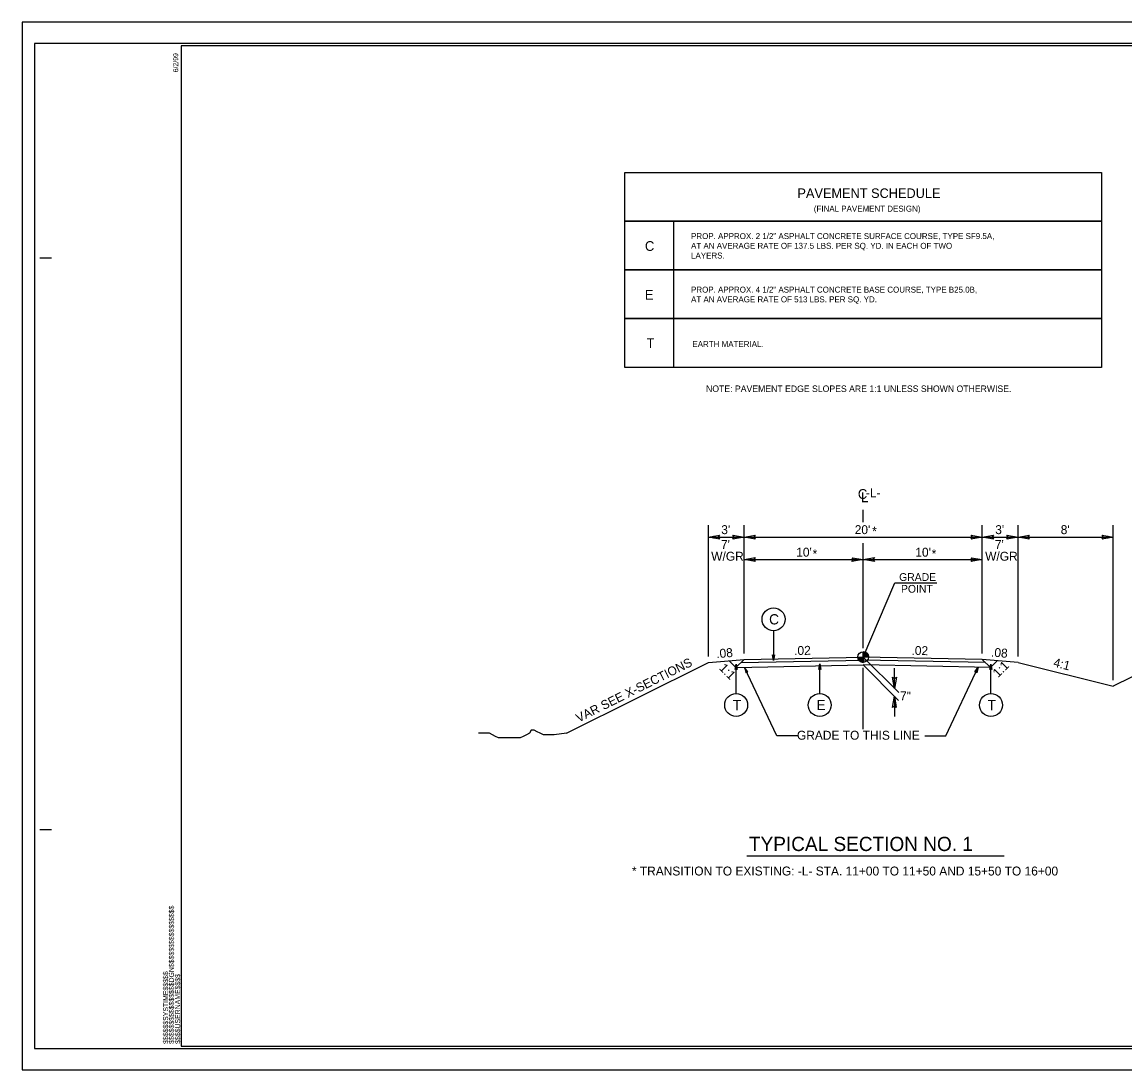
# Model space of a CAD drawing. Extents: x 573793 to 573946, y -53322 to -53234.
# Drawn here: x 573793.4 to 573886, y -53321.6 to -53233.6 of the extents above; entities that cross this region are included whole.
import ezdxf

# ---------------------------------------------------------------- set-up
doc = ezdxf.new("R2010")
doc.units = 0
for name, color, linetype in [('Prop Pavement Schedule Description CELL', 7, 'Continuous'), ('Sheet Cutting Line CELL', 7, 'Continuous'), ('Sheet Plot Border Inside CELL', 7, 'Continuous'), ('Sheet Plot Border Outside CELL', 7, 'Continuous'), ('Sheet Typical CELL', 7, 'Continuous'), ('Typical Grade Point Symbol CELL', 7, 'Continuous'), ('Typical ID Circle CELL', 7, 'Continuous'), ('Typical Pavement Slope CELL', 7, 'Continuous'), ('Typical Pavement Slope Information CELL', 7, 'Continuous'), ('Typical Shoulder Slope CELL', 7, 'Continuous'), ('Typical Slope Point Local CELL', 7, 'Continuous'), ('Typical Terminator CELL', 7, 'Continuous'), ('Typical Text Centerline CELL', 7, 'Continuous'), ('Typical Text General CELL', 7, 'Continuous'), ('Typical Text Grade Point CELL', 7, 'Continuous'), ('Typical Text ID Circle CELL', 7, 'Continuous'), ('Typical Text Label CELL', 7, 'Continuous')]:
    doc.layers.add(name, color=color, linetype=linetype)

msp = doc.modelspace()

# ---------------------------------------------------------------- linework, layer by layer
at = {"layer": 'Prop Pavement Schedule Description CELL'}
msp.add_line((573848.075, -53262.553), (573848.075, -53262.553), dxfattribs=at)
msp.add_lwpolyline([(573843.984, -53246.188), (573883.985, -53246.188), (573883.985, -53250.279), (573843.984, -53250.279)], close=True, dxfattribs=at)
for points in [[(573848.075, -53254.371), (573843.984, -53254.371), (573843.984, -53250.279), (573883.984, -53250.279), (573883.984, -53254.371), (573848.075, -53254.371), (573848.075, -53250.279)], [(573848.075, -53258.462), (573843.984, -53258.462), (573843.984, -53254.371), (573883.984, -53254.371), (573883.984, -53258.462), (573848.075, -53258.462), (573848.075, -53254.371)], [(573848.075, -53262.553), (573843.984, -53262.553), (573843.984, -53258.462), (573883.984, -53258.462), (573883.984, -53262.553), (573848.075, -53262.553), (573848.075, -53258.462)]]:
    msp.add_lwpolyline(points, dxfattribs=at)
at = {"layer": 'Sheet Cutting Line CELL'}
for p, q in [((573928.086, -53233.554), (573793.366, -53233.554)), ((573793.366, -53233.554), (573793.366, -53321.554)), ((573793.366, -53321.554), (573928.086, -53321.554))]:
    msp.add_line(p, q, dxfattribs=at)
at = {"layer": 'Sheet Plot Border Inside CELL'}
msp.add_lwpolyline([(573927.726, -53235.35), (573794.406, -53235.35), (573794.406, -53319.758), (573927.726, -53319.758)], close=True, dxfattribs=at)
at = {"layer": 'Sheet Plot Border Outside CELL'}
msp.add_lwpolyline([(573928.086, -53233.554), (573793.366, -53233.554), (573793.366, -53321.554), (573928.086, -53321.554)], close=True, dxfattribs=at)
at = {"layer": 'Sheet Typical CELL'}
for p, q in [((573794.846, -53253.354), (573795.846, -53253.354)), ((573794.846, -53301.354), (573795.846, -53301.354)), ((573806.726, -53319.554), (573806.726, -53319.554)), ((573806.726, -53319.554), (573806.726, -53319.554)), ((573806.726, -53319.554), (573806.726, -53319.554)), ((573806.726, -53319.554), (573806.726, -53319.554)), ((573806.726, -53319.554), (573806.726, -53319.554)), ((573806.726, -53319.554), (573806.726, -53319.554))]:
    msp.add_line(p, q, dxfattribs=at)
msp.add_lwpolyline([(573926.726, -53235.554), (573806.726, -53235.554), (573806.726, -53319.554), (573926.726, -53319.554)], close=True, dxfattribs=at)
msp.add_lwpolyline([(573809.726, -53319.554), (573809.726, -53319.554)], dxfattribs=at)
at = {"layer": 'Typical Grade Point Symbol CELL'}
for p, q in [((573863.537, -53286.879), (573863.984, -53286.879)), ((573863.983, -53287.326), (573863.984, -53286.879)), ((573863.984, -53286.879), (573863.983, -53287.326)), ((573863.984, -53286.879), (573863.984, -53286.431)), ((573864.432, -53286.879), (573863.984, -53286.879))]:
    msp.add_line(p, q, dxfattribs=at)
for points in [[(573863.539, -53286.879), (573863.539, -53286.928)], [(573863.548, -53286.879), (573863.548, -53286.98)], [(573863.557, -53286.879), (573863.557, -53287.012)], [(573863.566, -53286.879), (573863.566, -53287.039)], [(573863.575, -53286.879), (573863.575, -53287.06)], [(573863.584, -53286.879), (573863.584, -53287.079)], [(573863.593, -53286.879), (573863.593, -53287.096)], [(573863.602, -53286.879), (573863.602, -53287.112)], [(573863.611, -53286.879), (573863.611, -53287.126)], [(573863.619, -53286.879), (573863.619, -53287.138)], [(573863.628, -53286.879), (573863.628, -53287.15)], [(573863.637, -53286.879), (573863.637, -53287.161)], [(573863.646, -53286.879), (573863.646, -53287.172)], [(573863.655, -53286.879), (573863.655, -53287.182)], [(573863.664, -53286.879), (573863.664, -53287.192)], [(573863.673, -53286.879), (573863.673, -53287.201)], [(573863.682, -53286.879), (573863.682, -53287.209)], [(573863.691, -53286.879), (573863.691, -53287.217)], [(573863.7, -53286.879), (573863.7, -53287.225)], [(573863.709, -53286.879), (573863.709, -53287.232)], [(573863.718, -53286.879), (573863.718, -53287.239)], [(573863.727, -53286.879), (573863.727, -53287.245)], [(573863.736, -53286.879), (573863.736, -53287.251)], [(573863.745, -53286.879), (573863.745, -53287.257)], [(573863.754, -53286.879), (573863.754, -53287.263)], [(573863.763, -53286.879), (573863.763, -53287.268)], [(573863.772, -53286.879), (573863.772, -53287.273)], [(573863.781, -53286.879), (573863.781, -53287.278)], [(573863.79, -53286.879), (573863.79, -53287.282)], [(573863.798, -53286.879), (573863.798, -53287.286)], [(573863.807, -53286.879), (573863.807, -53287.29)], [(573863.816, -53286.879), (573863.816, -53287.294)], [(573863.825, -53286.879), (573863.825, -53287.298)], [(573863.834, -53286.879), (573863.834, -53287.301)], [(573863.843, -53286.879), (573863.843, -53287.304)], [(573863.852, -53286.879), (573863.852, -53287.307)], [(573863.861, -53286.879), (573863.861, -53287.309)], [(573863.87, -53286.879), (573863.87, -53287.312)], [(573863.879, -53286.879), (573863.879, -53287.314)], [(573863.888, -53286.879), (573863.888, -53287.316)], [(573863.897, -53286.879), (573863.897, -53287.318)], [(573863.906, -53286.879), (573863.906, -53287.319)], [(573863.915, -53286.879), (573863.915, -53287.32)], [(573863.924, -53286.879), (573863.924, -53287.322)], [(573863.933, -53286.879), (573863.933, -53287.323)], [(573863.942, -53286.879), (573863.942, -53287.324)], [(573863.951, -53286.879), (573863.951, -53287.325)], [(573863.96, -53286.879), (573863.96, -53287.325)], [(573863.969, -53286.879), (573863.969, -53287.326)], [(573863.978, -53286.879), (573863.978, -53287.326), (573863.978, -53287.326)], [(573863.988, -53286.431), (573863.988, -53286.431), (573863.988, -53286.879)], [(573863.997, -53286.431), (573863.997, -53286.879)], [(573864.006, -53286.432), (573864.006, -53286.879)], [(573864.015, -53286.432), (573864.015, -53286.879)], [(573864.024, -53286.433), (573864.024, -53286.879)], [(573864.033, -53286.434), (573864.033, -53286.879)], [(573864.042, -53286.435), (573864.042, -53286.879)], [(573864.051, -53286.436), (573864.051, -53286.879)], [(573864.06, -53286.437), (573864.06, -53286.879)], [(573864.069, -53286.439), (573864.069, -53286.879)], [(573864.078, -53286.441), (573864.078, -53286.879)], [(573864.087, -53286.443), (573864.087, -53286.879)], [(573864.096, -53286.445), (573864.096, -53286.879)], [(573864.105, -53286.448), (573864.105, -53286.879)], [(573864.114, -53286.45), (573864.114, -53286.879)], [(573864.123, -53286.453), (573864.123, -53286.879)], [(573864.132, -53286.456), (573864.132, -53286.879)], [(573864.141, -53286.459), (573864.141, -53286.879)], [(573864.15, -53286.463), (573864.15, -53286.879)], [(573864.159, -53286.467), (573864.159, -53286.879)], [(573864.167, -53286.471), (573864.167, -53286.879)], [(573864.176, -53286.475), (573864.176, -53286.879)], [(573864.185, -53286.479), (573864.185, -53286.879)], [(573864.194, -53286.484), (573864.194, -53286.879)], [(573864.203, -53286.489), (573864.203, -53286.879)], [(573864.212, -53286.494), (573864.212, -53286.879)], [(573864.221, -53286.499), (573864.221, -53286.879)], [(573864.23, -53286.505), (573864.23, -53286.879)], [(573864.239, -53286.511), (573864.239, -53286.879)], [(573864.248, -53286.518), (573864.248, -53286.879)], [(573864.257, -53286.524), (573864.257, -53286.879)], [(573864.266, -53286.531), (573864.266, -53286.879)], [(573864.275, -53286.539), (573864.275, -53286.879)], [(573864.284, -53286.547), (573864.284, -53286.879)], [(573864.293, -53286.555), (573864.293, -53286.879)], [(573864.302, -53286.564), (573864.302, -53286.879)], [(573864.311, -53286.573), (573864.311, -53286.879)], [(573864.32, -53286.582), (573864.32, -53286.879)], [(573864.329, -53286.593), (573864.329, -53286.879)], [(573864.338, -53286.604), (573864.338, -53286.879)], [(573864.347, -53286.616), (573864.347, -53286.879)], [(573864.355, -53286.629), (573864.355, -53286.879)], [(573864.364, -53286.643), (573864.364, -53286.879)], [(573864.373, -53286.658), (573864.373, -53286.879)], [(573864.382, -53286.674), (573864.382, -53286.879)], [(573864.391, -53286.693), (573864.391, -53286.879)], [(573864.4, -53286.714), (573864.4, -53286.879)], [(573864.409, -53286.739), (573864.409, -53286.879)], [(573864.418, -53286.769), (573864.418, -53286.879)], [(573864.427, -53286.815), (573864.427, -53286.879)]]:
    msp.add_lwpolyline(points, dxfattribs=at)
msp.add_circle((573863.984, -53286.879), 0.448, dxfattribs=at)
for start, end in [(179.99048, 269.99048), (359.99048, 89.99048)]:
    msp.add_arc((573863.984, -53286.879), 0.448, start, end, dxfattribs=at)
at = {"layer": 'Typical ID Circle CELL'}
for p, q in [((573856.458, -53284.671), (573856.458, -53287.156)), ((573853.318, -53289.948), (573853.318, -53287.463)), ((573860.337, -53289.947), (573860.337, -53287.461)), ((573874.709, -53289.948), (573874.709, -53287.463))]:
    msp.add_line(p, q, dxfattribs=at)
for centre in [(573856.458, -53283.709), (573853.318, -53290.91), (573860.337, -53290.908), (573874.709, -53290.91)]:
    msp.add_circle(centre, 0.962, dxfattribs=at)
at = {"layer": 'Typical Pavement Slope CELL'}
for p, q in [((573853.984, -53287.079), (573863.984, -53286.879)), ((573873.984, -53287.079), (573863.984, -53286.879)), ((573852.728, -53287.184), (573853.304, -53287.759)), ((573853.984, -53287.079), (573853.304, -53287.759)), ((573853.304, -53287.759), (573863.998, -53287.545)), ((573853.728, -53287.335), (573863.989, -53287.13)), ((573874.665, -53287.759), (573863.971, -53287.545)), ((573874.241, -53287.335), (573863.989, -53287.13)), ((573873.984, -53287.079), (573874.665, -53287.759)), ((573875.241, -53287.184), (573874.665, -53287.759))]:
    msp.add_line(p, q, dxfattribs=at)
at = {"layer": 'Typical Pavement Slope Information CELL'}
for p, q in [((573863.984, -53275.55), (573863.984, -53274.508)), ((573850.984, -53286.829), (573850.984, -53275.791)), ((573853.984, -53286.579), (573853.984, -53275.791)), ((573873.984, -53286.579), (573873.984, -53275.791)), ((573876.984, -53286.829), (573876.984, -53275.791)), ((573884.984, -53288.828), (573884.984, -53275.791)), ((573850.984, -53276.807), (573853.984, -53276.807)), ((573853.984, -53276.807), (573873.984, -53276.807)), ((573863.984, -53286.129), (573863.984, -53277.302)), ((573873.984, -53276.807), (573876.984, -53276.807)), ((573876.984, -53276.807), (573884.984, -53276.807)), ((573853.984, -53278.699), (573863.984, -53278.699)), ((573863.984, -53278.699), (573873.984, -53278.699)), ((573863.984, -53286.879), (573866.638, -53280.643)), ((573863.984, -53286.879), (573866.966, -53289.861)), ((573856.744, -53293.486), (573854.02, -53287.745)), ((573863.971, -53287.545), (573866.953, -53290.527)), ((573863.984, -53292.931), (573863.984, -53287.795)), ((573866.613, -53289.507), (573866.613, -53287.813)), ((573870.913, -53293.486), (573873.64, -53287.739)), ((573866.599, -53290.174), (573866.599, -53291.867)), ((573858.496, -53293.486), (573856.744, -53293.486)), ((573869.161, -53293.486), (573870.913, -53293.486))]:
    msp.add_line(p, q, dxfattribs=at)
at = {"layer": 'Typical Shoulder Slope CELL'}
for p, q in [((573850.984, -53287.329), (573853.984, -53287.079)), ((573876.984, -53287.329), (573873.984, -53287.079))]:
    msp.add_line(p, q, dxfattribs=at)
at = {"layer": 'Typical Slope Point Local CELL'}
for p, q in [((573898.6, -53282.52), (573884.983, -53289.328)), ((573839.081, -53293.281), (573850.984, -53287.329)), ((573876.984, -53287.329), (573884.983, -53289.328))]:
    msp.add_line(p, q, dxfattribs=at)
msp.add_lwpolyline([(573839.081, -53293.281), (573838.044, -53293.41), (573837.784, -53293.41), (573837.395, -53293.41), (573837.135, -53293.41), (573836.876, -53293.281), (573836.617, -53293.151), (573836.357, -53293.02), (573836.098, -53293.02), (573835.968, -53293.281), (573835.709, -53293.41), (573835.449, -53293.54), (573835.19, -53293.669), (573834.931, -53293.669), (573834.671, -53293.669), (573834.412, -53293.669), (573834.153, -53293.669), (573833.893, -53293.669), (573833.634, -53293.669), (573833.375, -53293.669), (573833.115, -53293.54), (573832.856, -53293.41), (573832.597, -53293.281), (573832.207, -53293.281), (573831.948, -53293.281), (573831.688, -53293.281)], dxfattribs=at)
at = {"layer": 'Typical Terminator CELL'}
for points in [[(573851.922, -53276.968), (573850.984, -53276.807), (573851.927, -53276.64), (573851.807, -53276.807)], [(573851.453, -53276.888), (573850.984, -53276.807), (573851.456, -53276.724), (573851.396, -53276.807)], [(573853.047, -53276.646), (573853.984, -53276.807), (573853.042, -53276.974), (573853.162, -53276.807)], [(573854.922, -53276.968), (573853.984, -53276.807), (573854.927, -53276.64), (573854.807, -53276.807)], [(573873.047, -53276.646), (573873.984, -53276.807), (573873.042, -53276.974), (573873.162, -53276.807)], [(573874.922, -53276.968), (573873.984, -53276.807), (573874.927, -53276.64), (573874.807, -53276.807)], [(573876.047, -53276.646), (573876.984, -53276.807), (573876.042, -53276.974), (573876.162, -53276.807)], [(573877.922, -53276.968), (573876.984, -53276.807), (573877.927, -53276.64), (573877.807, -53276.807)], [(573884.047, -53276.646), (573884.984, -53276.807), (573884.042, -53276.974), (573884.162, -53276.807)], [(573884.516, -53276.726), (573884.984, -53276.807), (573884.513, -53276.89), (573884.573, -53276.807)], [(573854.922, -53278.861), (573853.984, -53278.699), (573854.927, -53278.533), (573854.807, -53278.699)], [(573863.047, -53278.538), (573863.984, -53278.699), (573863.042, -53278.866), (573863.162, -53278.699)], [(573864.922, -53278.861), (573863.984, -53278.699), (573864.927, -53278.533), (573864.807, -53278.699)], [(573873.047, -53278.538), (573873.984, -53278.699), (573873.042, -53278.866), (573873.162, -53278.699)], [(573856.539, -53286.688), (573856.458, -53287.156), (573856.375, -53286.685), (573856.458, -53286.745)], [(573853.237, -53287.932), (573853.318, -53287.463), (573853.401, -53287.934), (573853.318, -53287.874)], [(573854.294, -53288.134), (573854.02, -53287.745), (573854.147, -53288.206), (573854.196, -53288.117)], [(573860.257, -53287.93), (573860.337, -53287.461), (573860.421, -53287.933), (573860.337, -53287.873)], [(573873.366, -53288.128), (573873.64, -53287.739), (573873.513, -53288.2), (573873.464, -53288.11)], [(573874.628, -53287.932), (573874.709, -53287.463), (573874.792, -53287.934), (573874.709, -53287.874)], [(573866.774, -53288.57), (573866.613, -53289.507), (573866.446, -53288.565), (573866.613, -53288.684)], [(573866.438, -53291.111), (573866.599, -53290.174), (573866.766, -53291.116), (573866.599, -53290.996)]]:
    msp.add_lwpolyline(points, close=True, dxfattribs=at)
at = {"layer": 'Typical Text Grade Point CELL'}
msp.add_line((573866.638, -53280.643), (573870.176, -53280.643), dxfattribs=at)
at = {"layer": 'Typical Text Label CELL'}
msp.add_line((573854.226, -53303.569), (573875.83, -53303.569), dxfattribs=at)

# ---------------------------------------------------------------- texts
at = {"layer": 'Prop Pavement Schedule Description CELL'}
for s, height, p in [('PAVEMENT SCHEDULE', 0.8, (573858.465, -53248.326)), ('PROP. APPROX. 2 1/2" ASPHALT CONCRETE SURFACE COURSE, TYPE SF9.5A,', 0.5, (573849.533, -53251.779)), ('C', 0.817, (573845.659, -53252.771)), ('AT AN AVERAGE RATE OF 137.5 LBS. PER SQ. YD. IN EACH OF TWO ', 0.5, (573849.533, -53252.595)), ('LAYERS.', 0.5, (573849.533, -53253.411)), ('E', 0.817, (573845.653, -53256.863)), ('PROP. APPROX. 4 1/2" ASPHALT CONCRETE BASE COURSE, TYPE B25.0B,', 0.5, (573849.533, -53256.275)), ('AT AN AVERAGE RATE OF 513 LBS. PER SQ. YD.', 0.5, (573849.533, -53257.091)), ('T', 0.8, (573845.799, -53260.915)), ('EARTH MATERIAL.', 0.5, (573849.647, -53260.85)), ('NOTE: PAVEMENT EDGE SLOPES ARE 1:1 UNLESS SHOWN OTHERWISE.', 0.54417, (573850.793, -53264.618))]:
    msp.add_text(s, height=height, dxfattribs=at).set_placement(p)
at = {"layer": 'Sheet Typical CELL'}
for s, p in [('6/2/99', (573806.474, -53237.774)), ('$$$$$$$$$$$$$$$$DGN$$$$$$$$$$$$$$$$', (573806.114, -53319.365)), ('$$$$$$SYSTIME$$$$$', (573805.63, -53319.365)), ('$$$$USERNAME$$$$', (573806.64, -53319.364))]:
    msp.add_text(s, height=0.42, rotation=90, dxfattribs=at).set_placement(p)
at = {"layer": 'Typical Pavement Slope CELL'}
msp.add_text('(FINAL PAVEMENT DESIGN)', height=0.5, dxfattribs=at).set_placement((573859.841, -53249.475))
for rotation, p in [(315, (573851.839, -53287.866)), (45, (573875.302, -53288.643))]:
    msp.add_text('1:1', height=0.75, rotation=rotation, dxfattribs=at).set_placement(p)
at = {"layer": 'Typical Pavement Slope Information CELL'}
for s, p in [('-L-', (573864.215, -53273.467)), ("3'", (573852.069, -53276.557)), ("20'", (573863.272, -53276.557)), ("3'", (573875.069, -53276.557)), ("8'", (573880.569, -53276.557)), ('*', (573864.737, -53276.683)), ("7'", (573852.04, -53277.807)), ("7'", (573875.04, -53277.807)), ('W/GR', (573851.226, -53278.79)), ("10'", (573858.362, -53278.449)), ('*', (573859.737, -53278.576)), ("10'", (573868.362, -53278.449)), ('*', (573869.737, -53278.576)), ('W/GR', (573874.226, -53278.79)), ('* TRANSITION TO EXISTING: -L- STA. 11+00 TO 11+50 AND 15+50 TO 16+00', (573844.564, -53305.224))]:
    msp.add_text(s, height=0.75, dxfattribs=at).set_placement(p)
for s, rotation, p in [('.02', 1.14574, (573858.196, -53286.714)), ('.02', 358.85426, (573868.034, -53286.696)), ('.08', 4.76142, (573851.678, -53286.979)), ('.08', 355.23858, (573874.695, -53286.831)), ('7"', 358.85426, (573867.066, -53290.512))]:
    msp.add_text(s, height=0.75, rotation=rotation, dxfattribs=at).set_placement(p)
at = {"layer": 'Typical Slope Point Local CELL'}
for s, rotation, p in [('VAR SEE X-SECTIONS', 26.56596, (573840.092, -53292.389)), ('4:1', 345.96376, (573879.902, -53287.666))]:
    msp.add_text(s, height=0.75, rotation=rotation, dxfattribs=at).set_placement(p)
at = {"layer": 'Typical Text Centerline CELL'}
msp.add_text('C', height=0.82, dxfattribs=at).set_placement((573863.534, -53273.597))
msp.add_text('L', height=0.821, rotation=359.9469, dxfattribs=at).set_placement((573863.806, -53273.877))
at = {"layer": 'Typical Text General CELL'}
msp.add_text('GRADE TO THIS LINE', height=0.75, dxfattribs=at).set_placement((573858.423, -53293.822))
at = {"layer": 'Typical Text Grade Point CELL'}
for s, p in [('GRADE', (573867.002, -53280.487)), ('POINT', (573867.159, -53281.475))]:
    msp.add_text(s, height=0.6525, dxfattribs=at).set_placement(p)
at = {"layer": 'Typical Text ID Circle CELL'}
for s, p in [('C', (573856.085, -53284.14)), ('T', (573853.035, -53291.34)), ('E', (573860.066, -53291.339)), ('T', (573874.426, -53291.34))]:
    msp.add_text(s, height=0.861, dxfattribs=at).set_placement(p)
at = {"layer": 'Typical Text Label CELL'}
msp.add_text('TYPICAL SECTION NO. 1 ', height=1.19356, dxfattribs=at).set_placement((573854.394, -53303.169))

doc.saveas('drawing.dxf')
